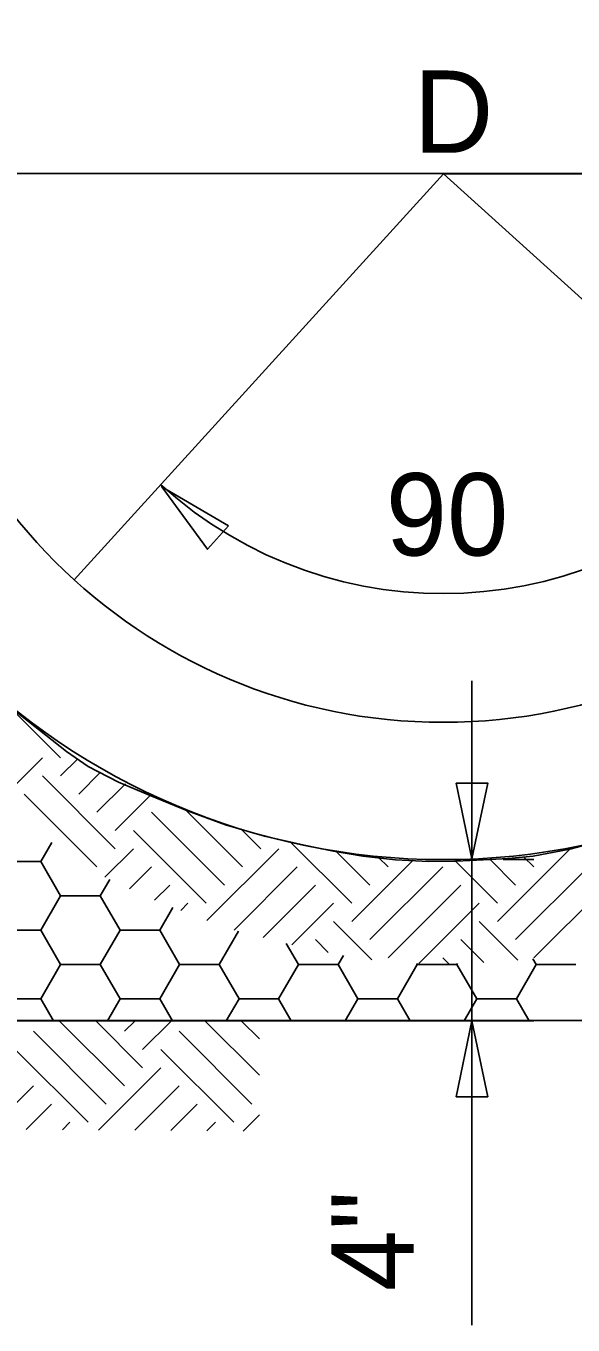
# Model space of a CAD drawing. Extents: x -439.1 to -407.9, y -458.1 to -436.2.
# Drawn here: x -434.155 to -433.159, y -445.635 to -443.269 of the extents above; entities that cross this region are included whole.
import ezdxf

# ---------------------------------------------------------------- set-up
doc = ezdxf.new("R2010")
doc.units = 0
doc.layers.add('Level 4', color=7, linetype='Continuous')
doc.layers.add('Level 45', color=7, linetype='Continuous')

msp = doc.modelspace()

# ---------------------------------------------------------------- linework, layer by layer
at = {"layer": 'Level 4'}
for p, q in [((-434.3952, -443.5372), (-432.3952, -443.5372)), ((-433.3947, -443.5378), (-434.0672, -444.2778)), ((-433.3952, -443.5372), (-433.3952, -443.5372)), ((-433.3952, -443.5372), (-433.3952, -443.5372)), ((-433.3947, -443.5378), (-432.3947, -443.5378)), ((-433.3947, -443.5378), (-432.6609, -444.2028)), ((-434.0667, -444.2782), (-434.0667, -444.2782)), ((-433.3429, -444.4613), (-433.3429, -445.6351)), ((-434.0921, -444.6017), (-434.1965, -444.4972)), ((-434.2026, -444.6791), (-434.1252, -444.6017)), ((-434.0921, -444.6348), (-434.0608, -444.6035)), ((-433.9926, -444.7674), (-434.1252, -444.6348)), ((-434.0589, -444.668), (-434.0191, -444.6282)), ((-434.0258, -444.7011), (-433.974, -444.6494)), ((-434.0258, -444.8006), (-434.1584, -444.668)), ((-433.9926, -444.7343), (-433.9289, -444.6706)), ((-433.7937, -444.8337), (-433.9263, -444.7011)), ((-433.7606, -444.8006), (-433.866, -444.6952)), ((-433.8269, -444.8668), (-433.9595, -444.7343)), ((-433.7275, -444.7674), (-433.7635, -444.7314)), ((-434.128, -444.791), (-434.1079, -444.7562)), ((-433.5617, -444.8668), (-433.6744, -444.7541)), ((-434.0114, -444.8193), (-433.9595, -444.7674)), ((-433.8254, -444.8985), (-433.6943, -444.7674)), ((-433.5286, -444.8337), (-433.5907, -444.7716)), ((-433.4954, -444.8006), (-433.5128, -444.7832)), ((-433.2966, -444.9), (-433.164, -444.7674)), ((-433.2303, -444.8006), (-433.2488, -444.7821)), ((-434.2001, -444.791), (-434.128, -444.791)), ((-434.128, -444.791), (-434.0919, -444.8535)), ((-433.9663, -444.8405), (-433.9263, -444.8006)), ((-433.7762, -444.9156), (-433.6612, -444.8006)), ((-433.5617, -444.9), (-433.4502, -444.7884)), ((-433.5286, -444.9331), (-433.396, -444.8006)), ((-433.2966, -444.8668), (-433.3742, -444.7892)), ((-433.2634, -444.8337), (-433.3105, -444.7866)), ((-433.2859, -444.7872), (-433.2304, -444.7872)), ((-433.2634, -444.9331), (-433.1308, -444.8006)), ((-434.0197, -444.8535), (-434.0024, -444.8235)), ((-434.128, -444.916), (-434.0919, -444.8535)), ((-434.0919, -444.8535), (-434.0197, -444.8535)), ((-434.0197, -444.8535), (-433.9836, -444.916)), ((-433.9208, -444.8613), (-433.8932, -444.8337)), ((-433.7234, -444.9291), (-433.628, -444.8337)), ((-433.4954, -444.9663), (-433.3629, -444.8337)), ((-433.2303, -444.9663), (-433.0977, -444.8337)), ((-433.9115, -444.916), (-433.8874, -444.8743)), ((-433.8731, -444.8799), (-433.86, -444.8668)), ((-433.6706, -444.9426), (-433.5949, -444.8668)), ((-433.4397, -444.9768), (-433.3297, -444.8668)), ((-433.5252, -444.9697), (-433.5949, -444.9)), ((-433.2593, -444.9704), (-433.3297, -444.9)), ((-434.2001, -444.916), (-434.128, -444.916)), ((-434.128, -444.916), (-434.0919, -444.9785)), ((-434.0197, -444.9785), (-433.9836, -444.916)), ((-433.9836, -444.916), (-433.9115, -444.916)), ((-433.9115, -444.916), (-433.8754, -444.9785)), ((-433.8032, -444.9785), (-433.7681, -444.9177)), ((-433.6811, -444.9399), (-433.6589, -444.9785)), ((-433.6047, -444.9565), (-433.628, -444.9331)), ((-433.3211, -444.9749), (-433.3629, -444.9331)), ((-433.5867, -444.9785), (-433.577, -444.9617)), ((-433.3852, -444.9771), (-433.396, -444.9663)), ((-433.2317, -444.9683), (-433.2259, -444.9785)), ((-434.128, -445.041), (-434.0919, -444.9785)), ((-434.0919, -444.9785), (-434.0197, -444.9785)), ((-434.0197, -444.9785), (-433.9836, -445.041)), ((-433.9115, -445.041), (-433.8754, -444.9785)), ((-433.8754, -444.9785), (-433.8032, -444.9785)), ((-433.8032, -444.9785), (-433.7671, -445.041)), ((-433.695, -445.041), (-433.6589, -444.9785)), ((-433.6589, -444.9785), (-433.5867, -444.9785)), ((-433.5867, -444.9785), (-433.5506, -445.041)), ((-433.4784, -445.041), (-433.4424, -444.9785)), ((-433.4435, -444.9765), (-433.4424, -444.9785)), ((-433.4424, -444.9785), (-433.3702, -444.9785)), ((-433.3702, -444.9785), (-433.3691, -444.9766)), ((-433.3702, -444.9785), (-433.3341, -445.041)), ((-433.2619, -445.041), (-433.2259, -444.9785)), ((-433.2259, -444.9785), (-433.1537, -444.9785)), ((-434.2001, -445.041), (-434.128, -445.041)), ((-434.128, -445.041), (-434.1049, -445.0809)), ((-434.0067, -445.0809), (-433.9836, -445.041)), ((-433.9836, -445.041), (-433.9115, -445.041)), ((-433.9115, -445.041), (-433.8884, -445.0809)), ((-433.7902, -445.0809), (-433.7671, -445.041)), ((-433.7671, -445.041), (-433.695, -445.041)), ((-433.695, -445.041), (-433.6719, -445.0809)), ((-433.5737, -445.0809), (-433.5506, -445.041)), ((-433.5506, -445.041), (-433.4784, -445.041)), ((-433.4784, -445.041), (-433.4554, -445.0809)), ((-433.3571, -445.0809), (-433.3341, -445.041)), ((-433.3341, -445.041), (-433.2619, -445.041)), ((-433.2619, -445.041), (-433.2389, -445.0809)), ((-435.8797, -445.0803), (-430.8697, -445.0803)), ((-435.7698, -445.0809), (-433.2304, -445.0809)), ((-433.9757, -445.1995), (-434.0944, -445.0809)), ((-433.9426, -445.1664), (-434.0281, -445.0809)), ((-433.9757, -445.1001), (-433.9565, -445.0809)), ((-433.9426, -445.1332), (-433.8902, -445.0809)), ((-433.7299, -445.1802), (-433.8292, -445.0809)), ((-433.7299, -445.1139), (-433.7629, -445.0809)), ((-434.0089, -445.2327), (-434.1414, -445.1001)), ((-433.7437, -445.2327), (-433.8763, -445.1001)), ((-434.042, -445.2658), (-434.1746, -445.1332)), ((-433.7768, -445.2658), (-433.9094, -445.1332)), ((-434.023, -445.2799), (-433.9094, -445.1664)), ((-434.2205, -445.2786), (-434.1414, -445.1995)), ((-433.9571, -445.2804), (-433.8763, -445.1995)), ((-434.1547, -445.2791), (-434.1083, -445.2327)), ((-433.8913, -445.2808), (-433.8431, -445.2327)), ((-433.7596, -445.2817), (-433.7299, -445.252)), ((-434.0888, -445.2795), (-434.0752, -445.2658)), ((-433.8254, -445.2812), (-433.81, -445.2658))]:
    msp.add_line(p, q, dxfattribs=at)
for points in [[(-433.7861, -444.1795), (-433.9079, -444.1079), (-433.8247, -444.222)], [(-433.3716, -444.6478), (-433.3429, -444.7861), (-433.3141, -444.6478)], [(-433.3141, -445.2192), (-433.3429, -445.0809), (-433.3716, -445.2192)]]:
    msp.add_lwpolyline(points, close=True, dxfattribs=at)
for points in [[(-433.2316, -444.7808), (-433.2765, -444.785), (-433.3216, -444.7875), (-433.3717, -444.7899), (-433.4217, -444.7908), (-433.4819, -444.7879), (-433.5417, -444.7808), (-433.5952, -444.7716), (-433.6485, -444.7608), (-433.7207, -444.7443), (-433.7919, -444.7241), (-433.8606, -444.6987), (-433.9286, -444.6707), (-433.9866, -444.6462), (-434.042, -444.6174), (-434.0811, -444.5902), (-434.1187, -444.5607), (-434.1505, -444.5357), (-434.1821, -444.5106)], [(-433.0982, -444.7508), (-433.1645, -444.768), (-433.2316, -444.7808)]]:
    msp.add_lwpolyline(points, dxfattribs=at)
for radius in [1.25, 1.25, 1, 1]:
    msp.add_circle((-433.3952, -443.5372), radius, dxfattribs=at)
msp.add_arc((-433.3952, -443.5372), 0.7655, 227.8173, 317.8173, dxfattribs=at)

# ---------------------------------------------------------------- texts
for s, p in [('D', (-433.4488, -443.4997)), ('90', (-433.4998, -444.2333))]:
    msp.add_text(s, height=0.15, dxfattribs=at).set_placement(p)
at = {"layer": 'Level 45'}
msp.add_text('4"', height=0.15, rotation=90, dxfattribs=at).set_placement((-433.4489, -445.5736))

doc.saveas('drawing.dxf')
